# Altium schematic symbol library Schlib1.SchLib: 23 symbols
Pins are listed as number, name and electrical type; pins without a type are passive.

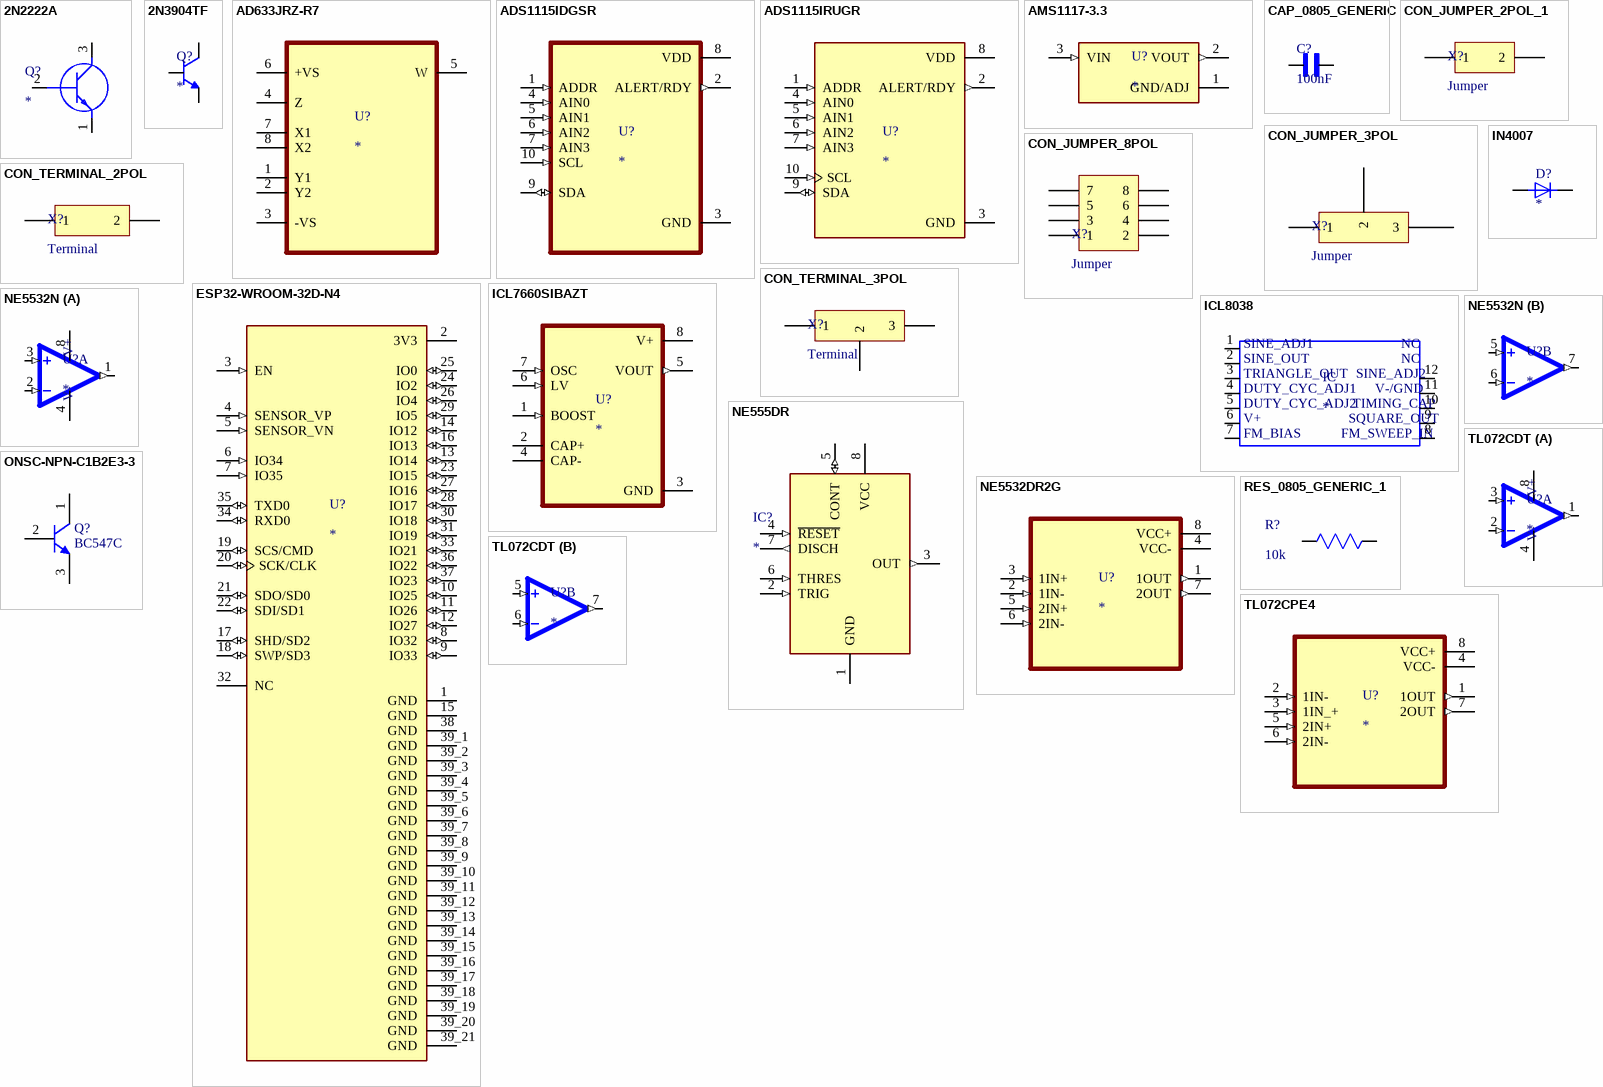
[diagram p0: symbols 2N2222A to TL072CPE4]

## 2N2222A
designator Q?
Transistor BJT NPN; Manufacturer_Name: Diotec; Manufacturer_Part_Number: 2N2222A
footprint 2N2222A
pins: 1 E, 2 B, 3 C

## 2N3904TF
designator Q?
Transistor General Purpose BJT NPN 40 Volt 0.2 Amp 3-Pin TO-92 Tape And Reel; MF: Fairchild Semiconductor; MP: 2N3904TF
footprint TO92254P520H877-3
pins: 1 E, 2 B, 3 C

## AD633JRZ-R7
designator U?
Analog Multiplier 4-Quadrant 8-SOIC; MF: Analog Devices; MP: AD633AR
footprint SOIC127P600X175-8N
pins: 1 Y1, 2 Y2, 3 -VS (power), 4 Z, 5 W, 6 +VS (power), 7 X1, 8 X2

## ADS1115IDGSR
designator U?
16-bit, 860-SPS, 4-channel, delta-sigma ADC with PGA, oscillator, VREF, comparator and I2C; MF: Texas Instruments; MP: ADS1115IDGSR
footprint SOP50P490X110-10N
pins: 1 ADDR (in), 2 ALERT/RDY (out), 3 GND (power), 4 AIN0 (in), 5 AIN1 (in), 6 AIN2 (in), 7 AIN3 (in), 8 VDD (power), 9 SDA (io), 10 SCL (in)

## ADS1115IRUGR
designator U?
16-bit, 860-SPS, 4-channel, delta-sigma ADC with PGA, oscillator, VREF, comparator and I2C; MF: Texas Instruments; MP: ADS1115IRUGR
footprint IC_ADS1115IRUGR
pins: 1 ADDR (in), 2 ALERT/RDY (out), 3 GND (power), 4 AIN0 (in), 5 AIN1 (in), 6 AIN2 (in), 7 AIN3 (in), 8 VDD (power), 9 SDA (io), 10 SCL (in)

## AMS1117-3.3
designator U?
LDO Voltage Regulators 800MA LDO LINEAR REG; MF: ams AG; MP: AMS1117-3.3
footprint SOT229P700X180-4N
pins: 1 GND/ADJ (power), 2 VOUT (out), 3 VIN (in)

## CAP_0805_GENERIC
designator C?, comment 100nF
0.1 ÂµF Â±10% 50V Ceramic Capacitor X7R 0805 (2012 Metric); MF: Samsung Electro-Mechanics; MP: CL21B104KBCNNNC
footprint CAPC2012X95N
pins: 1, 2

## CON_JUMPER_2POL_1
designator X?, comment Jumper
Manufacturer_Name: Yageo; Manufacturer_Part_Number: RC0805FR-0710KL; Value: 10k
footprint CON_JUMPER_2POL (Jumper)
pins: 1, 2

## CON_JUMPER_3POL
designator X?, comment Jumper
Manufacturer_Name: Yageo; Manufacturer_Part_Number: RC0805FR-0710KL; Value: 10k
footprint CON_JUMPER_3POL (Jumper)
pins: 1, 2, 3

## CON_JUMPER_8POL
designator X?, comment Jumper
Manufacturer_Name: Yageo; Manufacturer_Part_Number: RC0805FR-0710KL; Value: 10k
footprint CON_JUMPER_8POL (Jumper)
pins: 1, 2, 3, 4, 5, 6, 7, 8

## CON_TERMINAL_2POL
designator X?, comment Terminal
Terminal Screw; Manufacturer_Name: Yageo; Manufacturer_Part_Number: RC0805FR-0710KL; Value: 10k
footprint CON_TERMINAL_2POL (Terminal Screw)
pins: 1, 2

## CON_TERMINAL_3POL
designator X?, comment Terminal
Terminal block; Manufacturer_Name: Yageo; Manufacturer_Part_Number: RC0805FR-0710KL; Value: 10k
footprint CON_TERMINAL_3POL (Terminal Screw)
pins: 1, 2, 3

## ESP32-WROOM-32D-N4
designator U?
Bluetooth, WiFi 802.11b/g/n, Bluetooth v4.2 +EDR, Class 1, 2 and 3 Transceiver Module 2.4GHz ~ 2.5GHz Integrated, Trace Surface Mount; MF: Espressif Systems; MP: ESP32-WROOM-32D-N4
footprint MODULE_ESP32-WROOM-32D-N4
pins: 1 GND (power), 2 3V3 (power), 3 EN (in), 4 SENSOR_VP (in), 5 SENSOR_VN (in), 6 IO34 (in), 7 IO35 (in), 8 IO32 (io), 9 IO33 (io), 10 IO25 (io), 11 IO26 (io), 12 IO27 (io), 13 IO14 (io), 14 IO12 (io), 15 GND (power), 16 IO13 (io), 17 SHD/SD2 (io), 18 SWP/SD3 (io), 19 SCS/CMD (io), 20 SCK/CLK (io), 21 SDO/SD0 (io), 22 SDI/SD1 (io), 23 IO15 (io), 24 IO2 (io), 25 IO0 (io), 26 IO4 (io), 27 IO16 (io), 28 IO17 (io), 29 IO5 (io), 30 IO18 (io), 31 IO19 (io), 32 NC, 33 IO21 (io), 34 RXD0 (io), 35 TXD0 (io), 36 IO22 (io), 37 IO23 (io), 38 GND (power), 39_1 GND (power), 39_2 GND (power), 39_3 GND (power), 39_4 GND (power), 39_5 GND (power), 39_6 GND (power), 39_7 GND (power), 39_8 GND (power), 39_9 GND (power), 39_10 GND (power), 39_11 GND (power), 39_12 GND (power), 39_13 GND (power), 39_14 GND (power), 39_15 GND (power), 39_16 GND (power), 39_17 GND (power), 39_18 GND (power), 39_19 GND (power), 39_20 GND (power), 39_21 GND (power)

## ICL7660SIBAZT
designator U?
Charge Pump Switching Regulator IC Positive or Negative Fixed -Vin, 2Vin 1 Output 45mA 8-SOIC (0.154, 3.90mm Width); MF: Renesas Electronics America Inc; MP: ICL7660SIBAZT
footprint SOIC127P600X175-8N
pins: 1 BOOST (in), 2 CAP+, 3 GND (power), 4 CAP-, 5 VOUT (out), 6 LV (in), 7 OSC (in), 8 V+ (power)

## ICL8038
designator IC
IC OSCILL GEN/VOLT CONTROL 14DIP; MF: Renesas Electronics; MP: ICL8038
footprint ICL8038
pins: 1, 2, 3, 4, 5, 6, 7, 8, 9, 10, 11, 12

## IN4007
designator D?
Diode Standard 1000 V 1A Through Hole DO-204AL (DO-41); MF: Vishay Semiconductor; MP: IN4007
footprint DIOAD1070W78L470D235P
pins: A, C

## NE555DR
designator IC?
Integrated Circuit; Manufacturer_Name: Texas Instruments; Manufacturer_Part_Number: NE555DR
footprint SOIC127P600X175-8N
pins: 1 GND (power), 2 TRIG (in), 3 OUT (out), 4 ~{RESET} (in), 5 CONT (io), 6 THRES (in), 7 DISCH (out), 8 VCC (power)

## NE5532DR2G
designator U?
NE Series 9 V/us 22 V SMT Dual Low Noise Operational Amplifier - SOIC-16W; MP: NE5532DR2G; MF: ON Semiconductor
footprint SOIC127P599X175-8N
pins: 1 1OUT (out), 2 1IN- (in), 3 1IN+ (in), 4 VCC- (power), 5 2IN+ (in), 6 2IN- (in), 7 2OUT (out), 8 VCC+ (power)

## NE5532N
designator U?
IC, OP AMP, DUAL; No. of Amplifiers: 2 Amplifier; Bandwidth: 10MHz; Slew Rate: 8V/Âµs; Supply Voltage Range: Â± 15V; Amplifier Case Style: DIP; No. of Pins: 8Pins; Operating Temperature Min: 0Â°C; Operating Temperature Max: 70Â°C; MSL: -; SVHC: No SVHC (1; MF: Fairchild Semiconductor; MP: NE5532N
footprint DIP766W45P254L1016H533Q8
part A pins: 1 OUTA (out), 2 -INA (in), 3 +INA (in), 4 V- (power), 8 V+ (power)
part B pins: 5 +INB (in), 6 -INB (in), 7 OUTB (out)

## ONSC-NPN-C1B2E3-3
designator Q?, comment BC547C
Amplifier Transistor, NPN Silicon, 3-Pin TO-92, Bulk Box; Manufacturer: On Semiconductor; IC Continuous (A): 0.1; fT Min (MHz): 150
footprint ONSC-TO-92-3-29-11 (TO, 3-Leads, Body Dia 4.7mm, Pitch 1.27mm)
pins: 1 C, 2 B, 3 E

## RES_0805_GENERIC_1
designator R?, comment 10k
Description; Manufacturer_Name: Yageo; Manufacturer_Part_Number: RC0805FR-0710KL
footprint RC0805N_YAG-M
pins: 1, 2

## TL072CDT
designator U?
Dual Low-Noise JFET-Input General-Purpose Operational Amplifier 8-SOIC 0 to 70; MF: STMicroelectronics; MP: TL072CD
footprint SOIC127P600X175-8N
part A pins: 1 OUT1 (out), 2 -IN1 (in), 3 +IN1 (in), 4 V- (power), 8 V+ (power)
part B pins: 5 +IN2 (in), 6 -IN2 (in), 7 OUT2 (out)

## TL072CPE4
designator U?
Dual Low-Noise JFET-Input General-Purpose Operational Amplifier 8-PDIP 0 to 70; MF: Texas Instruments; MP: TL072CPE4
footprint DIP794W45P254L959H508Q8
pins: 1 1OUT (out), 2 1IN- (in), 3 1IN_+ (in), 4 VCC- (power), 5 2IN+ (in), 6 2IN- (in), 7 2OUT (out), 8 VCC+ (power)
